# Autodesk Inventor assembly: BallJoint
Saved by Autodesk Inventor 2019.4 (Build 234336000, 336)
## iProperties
Created: 2020-02
Part Number: BallJoint
Document SubType Name: Assembly
Designer: Administrator
Title: BallJoint v14
Author: Administrator
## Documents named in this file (3)
- c:\worker\convert-fusion-r01\tmp\job-1\5\output\files\e4333473-a38b-4431-9958-ad24a2f67704\BallJoint v14_6.iam
- c:\worker\convert-fusion-r01\tmp\job-1\5\output\files\e4333473-a38b-4431-9958-ad24a2f67704\Component1_1.ipt
- c:\worker\convert-fusion-r01\tmp\job-1\5\output\files\e4333473-a38b-4431-9958-ad24a2f67704\Component2_1.ipt
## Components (2 placed, 2 different names)
1. Component1:1
2. Component2:1
